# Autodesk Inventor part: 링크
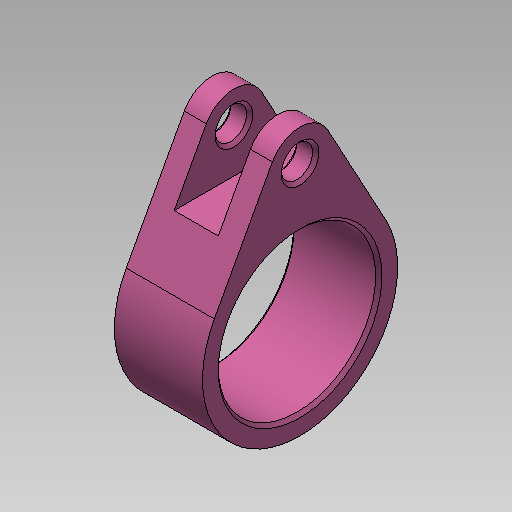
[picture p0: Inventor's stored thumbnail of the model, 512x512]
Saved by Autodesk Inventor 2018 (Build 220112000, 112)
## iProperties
Created: 2016-02
Part Number: 링크
Material: 강철, 연강
Document SubType Name: Modeling
Designer: test
Density: 1 g/cm^3
Appearance: 분홍색
Author: test
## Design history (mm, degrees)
sketch "스케치1"
  geometry: L1 (24.386, 4.394)-(7.398, 13.621); L2 (24.386, -4.394)-(7.398, -13.621); A1 r 15.5 centre (0, 0) between (7.398, 13.621) and (7.398, -13.621); A2 r 5 centre (22, 0) between (24.386, -4.394) and (24.386, 4.394); 1 further point
  constraints: 4 end point, 4 point on circle, 4 tangent, 2 centre point, 1 coincident, 1 horizontal alignment
  dimensions: "d0" = 22 distance of point (0, 0) A2.centre; "d1" = 15.5 radius of A1; "d2" = 5 radius of A2
extrude "돌출1" new body sketch "스케치1" stored distance "d3" = 14; taper "d4" = 0 deg
sketch "스케치2"
  geometry: C1 r 12.5 at (0, 0); 1 further point
  constraints: 1 centre point, 1 coincident
  dimensions: "d5" = 25 diameter of C1
extrude "돌출2" cut sketch "스케치2" extent not by distance; stored distance "d6" = 14; taper "d7" = 0 deg
sketch "스케치3"
  geometry: C1 r 2.5 at (22, 0); A1 r 5 centre (22, 0) between (24.386, -4.394) and (24.386, 4.394) reference; 1 further point
  constraints: 1 centre point, 1 coincident
  dimensions: "d8" = 5 diameter of C1
extrude "돌출3" cut sketch "스케치3" extent not by distance; stored distance "d9" = 14; taper "d10" = 0 deg
sketch "스케치4"
  geometry: L1 (24.386, -4.394)-(7.398, -13.621) reference; L2 (7.398, 13.621)-(24.386, 4.394) reference; L3 (15, 9.492)-(15, -9.492); C1 r 2.5 at (22, 0) reference; C2 r 12.5 at (0, 0) reference; A1 r 15.5 centre (0, 0) between (7.398, 13.621) and (7.398, -13.621) reference; A2 r 5 centre (22, 0) between (24.386, -4.394) and (24.386, 4.394) reference; 1 further point
  constraints: 2 end point, 2 point on line, 1 vertical
  dimensions: "d11" = 15 distance from line of L3 point (0, 0)
extrude "돌출4" cut sketch "스케치4" stored distance "d12" = 7; taper "d13" = 0 deg
chamfer "모따기1" distance "d14" = 0.5; stored, may be unused: second distance "d15" = 2, angle "d16" = 45 deg
node "솔리드1"
node "절단 모서리 투영1"
